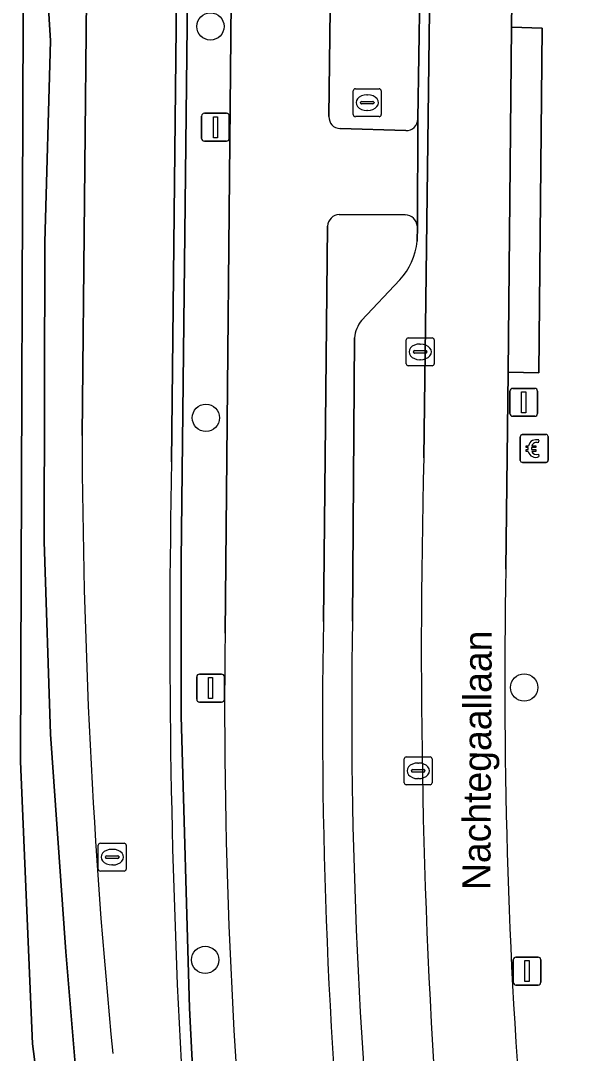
# Model space of a CAD drawing. Extents: x 161772 to 163126, y 383092 to 383917.
# Drawn here: x 161940.2 to 161960.46, y 383507.7 to 383544.69 of the extents above; entities that cross this region are included whole.
import ezdxf

# ---------------------------------------------------------------- set-up
doc = ezdxf.new("R2010")
doc.units = 0
for name, color, linetype in [('IMGEO_Berm_open', 7, 'Continuous'), ('IMGEO_Betaalautomaat', 7, 'Continuous'), ('IMGEO_Boom', 7, 'Continuous'), ('IMGEO_Brandkraan', 7, 'Continuous'), ('IMGEO_Erf', 7, 'Continuous'), ('IMGEO_Fietspad_gesloten', 7, 'Continuous'), ('IMGEO_Groenvoorziening', 7, 'Continuous'), ('IMGEO_Haag', 7, 'Continuous'), ('IMGEO_Kolk', 7, 'Continuous'), ('IMGEO_Lichtmast', 7, 'Continuous'), ('IMGEO_Oever', 7, 'Continuous'), ('IMGEO_Openbare_ruimte_label', 7, 'Continuous'), ('IMGEO_Parkeervlak_open', 7, 'Continuous'), ('IMGEO_Rijbaan_lokaal_gesloten', 7, 'Continuous'), ('IMGEO_Rioolput', 7, 'Continuous'), ('IMGEO_Voetpad_gesloten', 7, 'Continuous'), ('IMGEO_Voetpad_open', 7, 'Continuous'), ('IMGEO_Walbescherming', 7, 'Continuous'), ('IMGEO_Waterloop', 7, 'Continuous')]:
    doc.layers.add(name, color=color, linetype=linetype)

msp = doc.modelspace()

# ---------------------------------------------------------------- linework, layer by layer
at = {"layer": 'IMGEO_Berm_open'}
for points in [[(161951.912, 383604.915), (161951.886, 383596.8), (161951.872, 383592.233), (161951.241, 383541.255)], [(161954.429, 383541.167), (161954.499, 383545.71), (161953.401, 383545.747), (161953.535, 383554.682), (161954.635, 383554.682)], [(161951.636, 383540.825), (161953.994, 383540.753)], [(161953.972, 383537.743), (161951.608, 383537.749)], [(161951.191, 383537.333), (161951.042, 383523.171)], [(161954.397, 383536.79), (161954.406, 383537.324)], [(161952.408, 383533.957), (161953.776, 383535.409)], [(161952.081, 383523.187), (161952.158, 383533.334)]]:
    msp.add_lwpolyline(points, dxfattribs=at)
for centre, radius, start, end in [((161951.654, 383541.238), 0.414, 177.6641, 267.4773), ((161954.002, 383541.18), 0.427, 268.8952, 358.2709), ((161951.627, 383537.313), 0.437, 92.543, 177.3194), ((161953.948, 383537.284), 0.46, 4.9955, 87.0194), ((161952.062, 383537.01), 2.346, 316.9566, 354.619), ((161953.25, 383533.258), 1.094, 140.2763, 175.9941), ((162139.441, 383519.55), 188.433, 178.89906, 186.3382), ((162144.931, 383520.017), 192.876, 179.05837, 186.06909)]:
    msp.add_arc(centre, radius, start, end, dxfattribs=at)
at = {"layer": 'IMGEO_Betaalautomaat'}
for p, q in [((161958.092, 383528.943), (161958.092, 383529.784)), ((161958.092, 383529.784), (161958.092, 383528.943)), ((161958.167, 383529.867), (161959.008, 383529.867)), ((161959.008, 383529.867), (161958.167, 383529.867)), ((161959.091, 383529.793), (161959.091, 383528.952)), ((161959.091, 383528.952), (161959.091, 383529.793)), ((161958.375, 383529.331), (161958.375, 383529.399)), ((161958.496, 383529.399), (161958.496, 383529.331)), ((161958.754, 383529.672), (161958.737, 383529.572)), ((161958.741, 383529.166), (161958.763, 383529.079)), ((161959.017, 383528.868), (161958.176, 383528.868)), ((161958.176, 383528.868), (161959.017, 383528.868))]:
    msp.add_line(p, q, dxfattribs=at)
for points in [[(161958.375, 383529.399), (161958.306, 383529.399), (161958.306, 383529.468), (161958.385, 383529.468)], [(161958.507, 383529.468), (161958.654, 383529.468), (161958.654, 383529.399), (161958.496, 383529.399)], [(161958.38, 383529.262), (161958.306, 383529.262), (161958.306, 383529.331), (161958.375, 383529.331)], [(161958.496, 383529.331), (161958.654, 383529.331), (161958.654, 383529.262), (161958.51, 383529.262)]]:
    msp.add_lwpolyline(points, dxfattribs=at)
for centre, radius, start, end in [((161958.17, 383529.79), 0.0779, 92.4484, 184.2845), ((161958.17, 383529.79), 0.0779, 92.4484, 184.2845), ((161959.014, 383529.79), 0.0779, 2.4484, 94.2845), ((161959.014, 383529.79), 0.0779, 2.4484, 94.2845), ((161958.668, 383529.392), 0.293, 73.014, 165.0139), ((161958.674, 383529.405), 0.179, 69.3236, 159.5683), ((161958.641, 383529.317), 0.267, 191.8096, 297.0389), ((161958.674, 383529.332), 0.179, 202.7625, 291.8693), ((161958.17, 383528.946), 0.0779, 182.4484, 274.2845), ((161958.17, 383528.946), 0.0779, 182.4484, 274.2845), ((161959.014, 383528.946), 0.0779, 272.4484, 4.2845), ((161959.014, 383528.946), 0.0779, 272.4484, 4.2845)]:
    msp.add_arc(centre, radius, start, end, dxfattribs=at)
at = {"layer": 'IMGEO_Boom'}
for centre in [(161946.993, 383544.488), (161946.834, 383530.466), (161958.23, 383520.806), (161946.805, 383511.048)]:
    msp.add_circle(centre, 0.489, dxfattribs=at)
at = {"layer": 'IMGEO_Brandkraan'}
for p, q in [((161942.978, 383514.304), (161942.978, 383515.156)), ((161943.053, 383515.23), (161943.905, 383515.23)), ((161943.466, 383515.01), (161943.491, 383515.01)), ((161943.979, 383515.156), (161943.979, 383514.304)), ((161943.237, 383514.724), (161943.237, 383514.736)), ((161943.675, 383514.687), (161943.277, 383514.687)), ((161943.28, 383514.773), (161943.678, 383514.773)), ((161943.721, 383514.736), (161943.721, 383514.724)), ((161943.905, 383514.23), (161943.053, 383514.23)), ((161943.489, 383514.45), (161943.464, 383514.45))]:
    msp.add_line(p, q, dxfattribs=at)
for points in [[(161942.978, 383514.304), (161942.978, 383515.156)], [(161943.053, 383515.23), (161943.905, 383515.23)], [(161943.979, 383515.156), (161943.979, 383514.304)], [(161943.905, 383514.23), (161943.053, 383514.23)]]:
    msp.add_lwpolyline(points, dxfattribs=at)
for centre, radius, start, end in [((161943.055, 383515.154), 0.0765, 91.552, 178.448), ((161943.055, 383515.154), 0.0765, 91.552, 178.448), ((161943.903, 383515.154), 0.0765, 1.552, 88.448), ((161943.903, 383515.154), 0.0765, 1.552, 88.448), ((161943.277, 383514.733), 0.0403, 85.8775, 175.7526), ((161943.274, 383514.723), 0.0366, 178.938, 274.7102), ((161943.678, 383514.73), 0.043, 264.8664, 352.4533), ((161943.682, 383514.735), 0.0386, 1.7309, 96.639), ((161943.055, 383514.306), 0.0765, 181.552, 268.448), ((161943.055, 383514.306), 0.0765, 181.552, 268.448), ((161943.903, 383514.306), 0.0765, 271.552, 358.448), ((161943.903, 383514.306), 0.0765, 271.552, 358.448)]:
    msp.add_arc(centre, radius, start, end, dxfattribs=at)
for centre, major_axis, ratio, start_param, end_param in [((161943.465, 383514.73), (-0.387, 0.002), 0.722429, 4.712389, 7.853982), ((161943.49, 383514.73), (-0.39, 0.002), 0.717154, 1.570796, 4.712389)]:
    msp.add_ellipse(centre, major_axis=major_axis, ratio=ratio, start_param=start_param, end_param=end_param, dxfattribs=at)
at = {"layer": 'IMGEO_Erf'}
for points in [[(161941.105, 383546.503), (161941.272, 383543.971), (161941.058, 383536.754), (161941.036, 383526.041), (161941.266, 383519.14), (161941.82, 383511.344), (161942.547, 383502.593)], [(161942.399, 383529.835), (161942.572, 383546.7)]]:
    msp.add_lwpolyline(points, dxfattribs=at)
msp.add_arc((162175.622, 383530.29), 233.224, 180.11186, 185.55795, dxfattribs=at)
at = {"layer": 'IMGEO_Fietspad_gesloten'}
for points in [[(161951.241, 383541.255), (161951.872, 383592.233), (161951.886, 383596.8), (161948.41, 383596.774), (161947.874, 383555.079), (161947.754, 383546.646), (161947.521, 383522.757)], [(161953.994, 383540.753), (161951.636, 383540.825)], [(161954.406, 383537.324), (161954.429, 383541.167)], [(161951.608, 383537.749), (161953.972, 383537.743)], [(161951.042, 383523.171), (161951.191, 383537.333)]]:
    msp.add_lwpolyline(points, dxfattribs=at)
for centre, radius, start, end in [((161951.654, 383541.238), 0.414, 177.6641, 267.4773), ((161954.002, 383541.18), 0.427, 268.8952, 358.2709), ((161951.627, 383537.313), 0.437, 92.543, 177.3194), ((161953.948, 383537.284), 0.46, 4.9955, 87.0194), ((162139.441, 383519.55), 188.433, 178.89906, 186.3382), ((162145.525, 383520.033), 198.022, 179.21188, 186.15022)]:
    msp.add_arc(centre, radius, start, end, dxfattribs=at)
at = {"layer": 'IMGEO_Groenvoorziening'}
for points in [[(161952.31, 383465.637), (161954.925, 383455.453), (161955.312, 383455.554), (161952.311, 383467.345), (161951.236, 383472.113), (161950.07, 383477.977), (161949.296, 383482.301), (161948.409, 383488.069), (161947.799, 383492.559), (161946.904, 383500.464), (161946.378, 383506.728), (161946.244, 383509.317), (161945.946, 383519.776), (161945.946, 383525.342), (161946.191, 383546.671), (161945.791, 383546.677), (161945.604, 383528.895)], [(161947.521, 383522.757), (161947.754, 383546.646), (161946.191, 383546.671), (161945.946, 383525.342), (161945.946, 383519.776), (161946.244, 383509.317), (161946.378, 383506.728), (161946.904, 383500.464), (161947.799, 383492.559), (161948.409, 383488.069), (161949.296, 383482.301), (161950.07, 383477.977), (161951.236, 383472.113), (161952.311, 383467.345), (161955.312, 383455.554), (161956.569, 383455.884), (161953.29, 383468.191), (161953.677, 383468.263), (161952.442, 383474.059)]]:
    msp.add_lwpolyline(points, dxfattribs=at)
for centre, radius, start, end in [((162238.178, 383522.738), 292.639, 178.79449, 183.14152), ((162145.525, 383520.033), 198.022, 179.21188, 186.15022)]:
    msp.add_arc(centre, radius, start, end, dxfattribs=at)
at = {"layer": 'IMGEO_Haag'}
msp.add_lwpolyline([(161952.31, 383465.637), (161954.925, 383455.453), (161955.312, 383455.554), (161952.311, 383467.345), (161951.236, 383472.113), (161950.07, 383477.977), (161949.296, 383482.301), (161948.409, 383488.069), (161947.799, 383492.559), (161946.904, 383500.464), (161946.378, 383506.728), (161946.244, 383509.317), (161945.946, 383519.776), (161945.946, 383525.342), (161946.191, 383546.671), (161945.791, 383546.677), (161945.604, 383528.895)], dxfattribs=at)
msp.add_arc((162238.178, 383522.738), 292.639, 178.79449, 183.14152, dxfattribs=at)
at = {"layer": 'IMGEO_Kolk'}
for p, q in [((161954.008, 383532.403), (161954.008, 383533.255)), ((161954.083, 383533.329), (161954.935, 383533.329)), ((161954.496, 383533.109), (161954.521, 383533.109)), ((161955.009, 383533.255), (161955.009, 383532.403)), ((161954.267, 383532.823), (161954.267, 383532.835)), ((161954.705, 383532.786), (161954.307, 383532.786)), ((161954.31, 383532.872), (161954.708, 383532.872)), ((161954.751, 383532.835), (161954.751, 383532.823)), ((161954.935, 383532.329), (161954.083, 383532.329)), ((161954.519, 383532.549), (161954.494, 383532.549)), ((161954.011, 383518.322), (161954.863, 383518.322)), ((161953.936, 383517.396), (161953.936, 383518.248)), ((161954.424, 383518.102), (161954.449, 383518.102)), ((161954.937, 383518.248), (161954.937, 383517.396)), ((161954.195, 383517.816), (161954.195, 383517.828)), ((161954.633, 383517.779), (161954.235, 383517.779)), ((161954.238, 383517.865), (161954.636, 383517.865)), ((161954.447, 383517.542), (161954.422, 383517.542)), ((161954.679, 383517.828), (161954.679, 383517.816)), ((161954.863, 383517.322), (161954.011, 383517.322))]:
    msp.add_line(p, q, dxfattribs=at)
for points in [[(161954.008, 383532.403), (161954.008, 383533.255)], [(161954.083, 383533.329), (161954.935, 383533.329)], [(161955.009, 383533.255), (161955.009, 383532.403)], [(161954.935, 383532.329), (161954.083, 383532.329)], [(161954.011, 383518.322), (161954.863, 383518.322)], [(161953.936, 383517.396), (161953.936, 383518.248)], [(161954.937, 383518.248), (161954.937, 383517.396)], [(161954.863, 383517.322), (161954.011, 383517.322)]]:
    msp.add_lwpolyline(points, dxfattribs=at)
for centre, radius, start, end in [((161954.085, 383533.253), 0.0765, 91.552, 178.448), ((161954.085, 383533.253), 0.0765, 91.552, 178.448), ((161954.933, 383533.253), 0.0765, 1.552, 88.448), ((161954.933, 383533.253), 0.0765, 1.552, 88.448), ((161954.307, 383532.832), 0.0403, 85.8775, 175.7526), ((161954.304, 383532.822), 0.0366, 178.938, 274.7102), ((161954.708, 383532.829), 0.043, 264.8664, 352.4533), ((161954.712, 383532.834), 0.0386, 1.7309, 96.639), ((161954.085, 383532.405), 0.0765, 181.552, 268.448), ((161954.085, 383532.405), 0.0765, 181.552, 268.448), ((161954.933, 383532.405), 0.0765, 271.552, 358.448), ((161954.933, 383532.405), 0.0765, 271.552, 358.448), ((161954.013, 383518.246), 0.0765, 91.552, 178.448), ((161954.013, 383518.246), 0.0765, 91.552, 178.448), ((161954.861, 383518.246), 0.0765, 1.552, 88.448), ((161954.861, 383518.246), 0.0765, 1.552, 88.448), ((161954.235, 383517.825), 0.0403, 85.8775, 175.7526), ((161954.232, 383517.815), 0.0366, 178.938, 274.7102), ((161954.636, 383517.822), 0.043, 264.8664, 352.4533), ((161954.64, 383517.827), 0.0386, 1.7309, 96.639), ((161954.013, 383517.398), 0.0765, 181.552, 268.448), ((161954.013, 383517.398), 0.0765, 181.552, 268.448), ((161954.861, 383517.398), 0.0765, 271.552, 358.448), ((161954.861, 383517.398), 0.0765, 271.552, 358.448)]:
    msp.add_arc(centre, radius, start, end, dxfattribs=at)
for centre, major_axis, ratio, start_param, end_param in [((161954.495, 383532.829), (-0.387, 0.002), 0.722429, 4.712389, 7.853982), ((161954.52, 383532.829), (-0.39, 0.002), 0.717154, 1.570796, 4.712389), ((161954.423, 383517.822), (-0.387, 0.002), 0.722429, 4.712389, 7.853982), ((161954.448, 383517.822), (-0.39, 0.002), 0.717154, 1.570796, 4.712389)]:
    msp.add_ellipse(centre, major_axis=major_axis, ratio=ratio, start_param=start_param, end_param=end_param, dxfattribs=at)
at = {"layer": 'IMGEO_Lichtmast'}
for p, q in [((161946.679, 383540.476), (161946.679, 383541.276)), ((161946.679, 383541.276), (161946.679, 383540.476)), ((161946.779, 383541.376), (161947.569, 383541.376)), ((161947.569, 383541.376), (161946.779, 383541.376)), ((161947.669, 383541.276), (161947.669, 383540.476)), ((161947.669, 383540.476), (161947.669, 383541.276)), ((161947.569, 383540.376), (161946.779, 383540.376)), ((161946.779, 383540.376), (161947.569, 383540.376)), ((161957.721, 383530.622), (161957.721, 383531.422)), ((161957.721, 383531.422), (161957.721, 383530.622)), ((161957.821, 383531.522), (161958.611, 383531.522)), ((161958.611, 383531.522), (161957.821, 383531.522)), ((161958.711, 383531.422), (161958.711, 383530.622)), ((161958.711, 383530.622), (161958.711, 383531.422)), ((161958.611, 383530.522), (161957.821, 383530.522)), ((161957.821, 383530.522), (161958.611, 383530.522)), ((161946.604, 383521.285), (161947.394, 383521.285)), ((161947.394, 383521.285), (161946.604, 383521.285)), ((161946.504, 383520.385), (161946.504, 383521.185)), ((161946.504, 383521.185), (161946.504, 383520.385)), ((161947.494, 383521.185), (161947.494, 383520.385)), ((161947.494, 383520.385), (161947.494, 383521.185)), ((161947.394, 383520.285), (161946.604, 383520.285)), ((161946.604, 383520.285), (161947.394, 383520.285)), ((161957.84, 383510.249), (161957.84, 383511.049)), ((161957.84, 383511.049), (161957.84, 383510.249)), ((161957.94, 383511.149), (161958.73, 383511.149)), ((161958.73, 383511.149), (161957.94, 383511.149)), ((161958.83, 383511.049), (161958.83, 383510.249)), ((161958.83, 383510.249), (161958.83, 383511.049)), ((161958.73, 383510.149), (161957.94, 383510.149)), ((161957.94, 383510.149), (161958.73, 383510.149))]:
    msp.add_line(p, q, dxfattribs=at)
for points in [[(161947.099, 383541.251), (161947.249, 383541.251), (161947.249, 383540.501), (161947.099, 383540.501), (161947.099, 383541.251)], [(161958.141, 383531.397), (161958.291, 383531.397), (161958.291, 383530.647), (161958.141, 383530.647), (161958.141, 383531.397)], [(161946.924, 383521.16), (161947.074, 383521.16), (161947.074, 383520.41), (161946.924, 383520.41), (161946.924, 383521.16)], [(161958.26, 383511.024), (161958.41, 383511.024), (161958.41, 383510.274), (161958.26, 383510.274), (161958.26, 383511.024)]]:
    msp.add_lwpolyline(points, dxfattribs=at)
for centre, start, end in [((161946.779, 383541.276), 90, 180), ((161946.779, 383541.276), 90, 180), ((161947.569, 383541.276), 0, 90), ((161947.569, 383541.276), 360, 90), ((161946.779, 383540.476), 180, 270), ((161946.779, 383540.476), 180, 270), ((161947.569, 383540.476), 270, 0), ((161947.569, 383540.476), 270, 0), ((161957.821, 383531.422), 90, 180), ((161957.821, 383531.422), 90, 180), ((161958.611, 383531.422), 0, 90), ((161958.611, 383531.422), 360, 90), ((161957.821, 383530.622), 180, 270), ((161957.821, 383530.622), 180, 270), ((161958.611, 383530.622), 270, 0), ((161958.611, 383530.622), 270, 0), ((161946.604, 383521.185), 90, 180), ((161946.604, 383521.185), 90, 180), ((161947.394, 383521.185), 0, 90), ((161947.394, 383521.185), 360, 90), ((161946.604, 383520.385), 180, 270), ((161946.604, 383520.385), 180, 270), ((161947.394, 383520.385), 270, 0), ((161947.394, 383520.385), 270, 0), ((161957.94, 383511.049), 90, 180), ((161957.94, 383511.049), 90, 180), ((161958.73, 383511.049), 0, 90), ((161958.73, 383511.049), 360, 90), ((161957.94, 383510.249), 180, 270), ((161957.94, 383510.249), 180, 270), ((161958.73, 383510.249), 270, 0), ((161958.73, 383510.249), 270, 0)]:
    msp.add_arc(centre, 0.1, start, end, dxfattribs=at)
at = {"layer": 'IMGEO_Oever'}
for points in [[(161940.297, 383548.164), (161940.197, 383518.161), (161940.619, 383508.044), (161941.134, 383504.086), (161943.663, 383486.452), (161945.749, 383474.834), (161947.621, 383464.578), (161949.881, 383456.393), (161949.424, 383455.702), (161946.464, 383454.608), (161945.714, 383454.585)], [(161949.442, 383454.684), (161950.513, 383455.316), (161950.771, 383455.831), (161950.677, 383456.756), (161949.178, 383462.026), (161947.545, 383469.712), (161946.155, 383476.296), (161944.658, 383485.032), (161944.118, 383488.713), (161943.43, 383494.214), (161942.547, 383502.593), (161941.82, 383511.344), (161941.266, 383519.14), (161941.036, 383526.041), (161941.058, 383536.754), (161941.272, 383543.971), (161941.105, 383546.503)]]:
    msp.add_lwpolyline(points, dxfattribs=at)
at = {"layer": 'IMGEO_Parkeervlak_open'}
for points in [[(161954.642, 383529.038), (161955.531, 383599.658)], [(161954.635, 383554.682), (161954.499, 383545.71), (161954.429, 383541.167), (161954.406, 383537.324), (161954.397, 383536.79)], [(161953.776, 383535.409), (161952.408, 383533.957)], [(161952.158, 383533.334), (161952.081, 383523.187)]]:
    msp.add_lwpolyline(points, dxfattribs=at)
for centre, radius, start, end in [((161952.062, 383537.01), 2.346, 316.9566, 354.619), ((161953.25, 383533.258), 1.094, 140.2763, 175.9941), ((162204.861, 383522.156), 250.314, 178.42461, 184.35465), ((162144.931, 383520.017), 192.876, 179.05837, 186.06909)]:
    msp.add_arc(centre, radius, start, end, dxfattribs=at)
at = {"layer": 'IMGEO_Rijbaan_lokaal_gesloten'}
for points in [[(161955.531, 383599.658), (161954.642, 383529.038)], [(161957.777, 383544.459), (161958.143, 383571.647), (161959.939, 383599.782)], [(161957.654, 383532.098), (161957.777, 383544.459)], [(161957.579, 383525.05), (161957.654, 383532.098)]]:
    msp.add_lwpolyline(points, dxfattribs=at)
for centre, radius, start, end in [((162204.861, 383522.156), 250.314, 178.42461, 184.35465), ((162165.736, 383520.949), 208.198, 178.87138, 184.84325)]:
    msp.add_arc(centre, radius, start, end, dxfattribs=at)
at = {"layer": 'IMGEO_Rioolput'}
for p, q in [((161952.112, 383541.328), (161952.112, 383542.18)), ((161952.187, 383542.254), (161953.039, 383542.254)), ((161952.6, 383542.034), (161952.625, 383542.034)), ((161953.113, 383542.18), (161953.113, 383541.328)), ((161952.371, 383541.748), (161952.371, 383541.76)), ((161952.809, 383541.711), (161952.411, 383541.711)), ((161952.414, 383541.797), (161952.812, 383541.797)), ((161952.855, 383541.76), (161952.855, 383541.748)), ((161953.039, 383541.254), (161952.187, 383541.254)), ((161952.623, 383541.474), (161952.598, 383541.474))]:
    msp.add_line(p, q, dxfattribs=at)
for points in [[(161952.112, 383541.328), (161952.112, 383542.18)], [(161952.187, 383542.254), (161953.039, 383542.254)], [(161953.113, 383542.18), (161953.113, 383541.328)], [(161953.039, 383541.254), (161952.187, 383541.254)]]:
    msp.add_lwpolyline(points, dxfattribs=at)
for centre, radius, start, end in [((161952.189, 383542.178), 0.0765, 91.552, 178.448), ((161952.189, 383542.178), 0.0765, 91.552, 178.448), ((161953.037, 383542.178), 0.0765, 1.552, 88.448), ((161953.037, 383542.178), 0.0765, 1.552, 88.448), ((161952.411, 383541.757), 0.0403, 85.8775, 175.7526), ((161952.408, 383541.747), 0.0366, 178.938, 274.7102), ((161952.812, 383541.754), 0.043, 264.8664, 352.4533), ((161952.816, 383541.759), 0.0386, 1.7309, 96.639), ((161952.189, 383541.33), 0.0765, 181.552, 268.448), ((161952.189, 383541.33), 0.0765, 181.552, 268.448), ((161953.037, 383541.33), 0.0765, 271.552, 358.448), ((161953.037, 383541.33), 0.0765, 271.552, 358.448)]:
    msp.add_arc(centre, radius, start, end, dxfattribs=at)
for centre, major_axis, ratio, start_param, end_param in [((161952.599, 383541.754), (-0.387, 0.002), 0.722429, 4.712389, 7.853982), ((161952.624, 383541.754), (-0.39, 0.002), 0.717154, 1.570796, 4.712389)]:
    msp.add_ellipse(centre, major_axis=major_axis, ratio=ratio, start_param=start_param, end_param=end_param, dxfattribs=at)
at = {"layer": 'IMGEO_Voetpad_gesloten'}
for points in [[(161945.604, 383528.895), (161945.791, 383546.677), (161946.191, 383546.671), (161947.754, 383546.646), (161947.874, 383555.079), (161946.301, 383555.108), (161945.901, 383555.116), (161946.517, 383601.159), (161946.917, 383601.157), (161947.274, 383601.155)], [(161942.927, 383569.61), (161942.7, 383554.967), (161942.695, 383554.606), (161942.585, 383547.511), (161942.578, 383547.077), (161942.572, 383546.7), (161942.399, 383529.835)]]:
    msp.add_lwpolyline(points, dxfattribs=at)
for centre, radius, start, end in [((162175.622, 383530.29), 233.224, 180.11186, 185.55795), ((162238.178, 383522.738), 292.639, 178.79449, 183.14152)]:
    msp.add_arc(centre, radius, start, end, dxfattribs=at)
at = {"layer": 'IMGEO_Voetpad_open'}
msp.add_lwpolyline([(161960.46, 383607.576), (161960.018, 383600.863), (161959.977, 383600.247), (161959.939, 383599.782), (161958.143, 383571.647), (161957.777, 383544.459), (161958.881, 383544.427), (161958.757, 383532.079), (161957.654, 383532.098), (161957.579, 383525.05)], dxfattribs=at)
msp.add_lwpolyline([(161957.777, 383544.459), (161957.654, 383532.098), (161958.757, 383532.079), (161958.881, 383544.427)], close=True, dxfattribs=at)
msp.add_arc((162165.736, 383520.949), 208.198, 178.87138, 184.84325, dxfattribs=at)
at = {"layer": 'IMGEO_Walbescherming'}
msp.add_lwpolyline([(161940.297, 383548.164), (161940.197, 383518.161), (161940.619, 383508.044), (161941.134, 383504.086), (161943.663, 383486.452), (161945.749, 383474.834), (161947.621, 383464.578), (161949.881, 383456.393)], dxfattribs=at)
at = {"layer": 'IMGEO_Waterloop'}
msp.add_lwpolyline([(161945.714, 383454.585), (161946.464, 383454.608), (161949.424, 383455.702), (161949.881, 383456.393), (161947.621, 383464.578), (161945.749, 383474.834), (161943.663, 383486.452), (161941.134, 383504.086), (161940.619, 383508.044), (161940.197, 383518.161), (161940.297, 383548.164), (161940.334, 383548.614), (161940.702, 383553.69), (161940.791, 383554.058), (161940.693, 383561.649), (161940.295, 383567.926)], dxfattribs=at)

# ---------------------------------------------------------------- texts
at = {"layer": 'IMGEO_Openbare_ruimte_label'}
msp.add_text('Nachtegaallaan', height=1, rotation=89.6562, dxfattribs=at).set_placement((161957.019, 383513.549))

doc.saveas('drawing.dxf')
